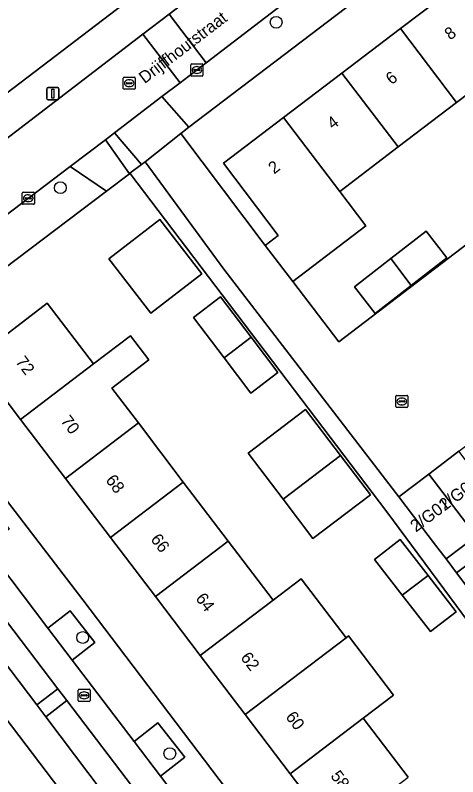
# Model space of a CAD drawing. Extents: x 160030 to 160839, y 385325 to 386450.
# Drawn here: x 160455.5 to 160492.1, y 385535.4 to 385598.3 of the extents above; entities that cross this region are included whole.
import ezdxf

# ---------------------------------------------------------------- set-up
doc = ezdxf.new("R2010")
doc.units = 0
for name, color, linetype in [('IMGEO_Berm_groen', 7, 'Continuous'), ('IMGEO_Boom', 7, 'Continuous'), ('IMGEO_Erf', 7, 'Continuous'), ('IMGEO_Fietspad_gesloten', 7, 'Continuous'), ('IMGEO_Groenvoorziening', 7, 'Continuous'), ('IMGEO_Kolk', 7, 'Continuous'), ('IMGEO_Lichtmast', 7, 'Continuous'), ('IMGEO_Openbare_ruimte_label', 7, 'Continuous'), ('IMGEO_Pand', 7, 'Continuous'), ('IMGEO_Pand_nummerreeks', 7, 'Continuous'), ('IMGEO_Parkeervlak_open', 7, 'Continuous'), ('IMGEO_Rijbaan_lokaal_gesloten', 7, 'Continuous'), ('IMGEO_Rijbaan_lokaal_open', 7, 'Continuous'), ('IMGEO_Rioolput', 7, 'Continuous'), ('IMGEO_Voetpad_open', 7, 'Continuous')]:
    doc.layers.add(name, color=color, linetype=linetype)

msp = doc.modelspace()

# ---------------------------------------------------------------- linework, layer by layer
at = {"layer": 'IMGEO_Berm_groen'}
msp.add_lwpolyline([(160447.13, 385554.756), (160457.308, 385541.366), (160459.033, 385542.706), (160443.342, 385563.345)], dxfattribs=at)
msp.add_lwpolyline([(160459.78, 385541.723), (160458.059, 385540.397), (160463.888, 385532.649), (160465.638, 385534.018)], close=True, dxfattribs=at)
at = {"layer": 'IMGEO_Boom'}
for centre in [(160477.081, 385597.751), (160459.249, 385584.086), (160461.094, 385546.937), (160468.294, 385537.344)]:
    msp.add_circle(centre, 0.489, dxfattribs=at)
at = {"layer": 'IMGEO_Erf'}
for points in [[(160541.325, 385643.407), (160500, 385611.993), (160469.864, 385589.083), (160469.192, 385588.563), (160476.184, 385579.322), (160477.257, 385580.137), (160472.72, 385586.106), (160477.69, 385589.884), (160482.522, 385593.557), (160487.355, 385597.231), (160492.187, 385600.904), (160497.019, 385604.577), (160500, 385606.843), (160501.851, 385608.25), (160503.572, 385609.559), (160502.858, 385610.499)], [(160440.459, 385581.006), (160500, 385626.337)], [(160496.829, 385594.796), (160491.998, 385591.123), (160487.165, 385587.449), (160482.333, 385583.776), (160484.501, 385580.924), (160478.458, 385576.33), (160482.263, 385571.356), (160495.041, 385581.104)], [(160464.999, 385585.276), (160464.955, 385585.243), (160463.068, 385583.814), (160446.182, 385571.066)], [(160499.726, 385539.086), (160486.228, 385557.31), (160464.999, 385585.276)], [(160481.957, 385530.81), (160478.243, 385535.687), (160474.529, 385540.564), (160470.814, 385545.441), (160467.1, 385550.318), (160463.386, 385555.194), (160459.672, 385560.071), (160455.957, 385564.949), (160452.138, 385569.963), (160458.158, 385574.548), (160461.977, 385569.533), (160465.036, 385571.862), (160466.558, 385569.862), (160463.5, 385567.533), (160465.693, 385564.654), (160469.407, 385559.778), (160473.122, 385554.901), (160476.836, 385550.025), (160479.148, 385551.785), (160482.861, 385546.907), (160483.062, 385547.06), (160486.776, 385542.184), (160484.264, 385540.271), (160487.978, 385535.394)], [(160445.996, 385569.716), (160461.114, 385550.049), (160484.853, 385518.765), (160498.893, 385500), (160500, 385498.52), (160507.161, 385489.347)], [(160493.605, 385555.304), (160491.129, 385553.423), (160491.983, 385552.267), (160494.561, 385554.205)]]:
    msp.add_lwpolyline(points, dxfattribs=at)
for points in [[(160463.243, 385578.212), (160467.466, 385581.469), (160470.929, 385576.979), (160466.71, 385573.725)], [(160486.547, 385578.231), (160489.472, 385580.494), (160491.182, 385578.282), (160488.24, 385576.006), (160485.254, 385573.697), (160483.543, 385575.908)], [(160472.486, 385575.066), (160475.01, 385571.746), (160477.225, 385568.83), (160474.988, 385567.13), (160472.774, 385570.044), (160470.249, 385573.367)], [(160477.659, 385558.354), (160474.764, 385562.164), (160479.512, 385565.772), (160482.404, 385561.965), (160484.865, 385558.725), (160480.117, 385555.117)], [(160487.498, 385550.438), (160485.217, 385553.371), (160487.332, 385555.017), (160489.631, 385552.062), (160491.96, 385549.068), (160489.827, 385547.444)]]:
    msp.add_lwpolyline(points, close=True, dxfattribs=at)
at = {"layer": 'IMGEO_Fietspad_gesloten'}
for points in [[(160472.998, 385528.276), (160467.524, 385535.472), (160465.348, 385538.333), (160460.22, 385545.074), (160458.213, 385547.717), (160453.099, 385554.455), (160450.953, 385557.282), (160445.661, 385564.255), (160443.639, 385566.902), (160443.094, 385567.626), (160440.675, 385570.838), (160437.024, 385575.695), (160434.488, 385579.069), (160434.209, 385579.434), (160431.957, 385582.38), (160424.67, 385591.91), (160423.01, 385594.08), (160417.542, 385601.244), (160415.698, 385603.667), (160409.13, 385612.299), (160407.497, 385614.445), (160405.943, 385616.479), (160403.696, 385619.461), (160402.039, 385616.699)], [(160439.79, 385567.957), (160441.538, 385565.717), (160443.342, 385563.345), (160459.033, 385542.706), (160459.78, 385541.723), (160465.638, 385534.018), (160466.586, 385532.772), (160475.085, 385521.593), (160475.646, 385520.856), (160480.979, 385513.841), (160481.709, 385512.882), (160498.314, 385491.117), (160500.146, 385488.707), (160503.656, 385484.09)]]:
    msp.add_lwpolyline(points, dxfattribs=at)
at = {"layer": 'IMGEO_Groenvoorziening'}
for points in [[(160460.068, 385549.13), (160458.213, 385547.717), (160460.22, 385545.074), (160462.101, 385546.514)], [(160467.303, 385539.888), (160465.348, 385538.333), (160467.524, 385535.472), (160469.523, 385537.051)]]:
    msp.add_lwpolyline(points, close=True, dxfattribs=at)
at = {"layer": 'IMGEO_Kolk'}
for p, q in [((160470.029, 385593.385), (160470.029, 385594.237)), ((160470.104, 385594.311), (160470.956, 385594.311)), ((160470.517, 385594.091), (160470.542, 385594.091)), ((160471.03, 385594.237), (160471.03, 385593.385)), ((160470.288, 385593.805), (160470.288, 385593.817)), ((160470.726, 385593.768), (160470.328, 385593.768)), ((160470.331, 385593.854), (160470.729, 385593.854)), ((160470.54, 385593.531), (160470.515, 385593.531)), ((160470.772, 385593.817), (160470.772, 385593.805)), ((160470.956, 385593.311), (160470.104, 385593.311)), ((160456.096, 385582.788), (160456.096, 385583.64)), ((160456.171, 385583.714), (160457.023, 385583.714)), ((160456.584, 385583.494), (160456.609, 385583.494)), ((160457.097, 385583.64), (160457.097, 385582.788)), ((160457.023, 385582.714), (160456.171, 385582.714)), ((160456.355, 385583.208), (160456.355, 385583.22)), ((160456.793, 385583.171), (160456.395, 385583.171)), ((160456.398, 385583.257), (160456.796, 385583.257)), ((160456.607, 385582.934), (160456.582, 385582.934)), ((160456.839, 385583.22), (160456.839, 385583.208)), ((160486.964, 385566.009), (160486.964, 385566.861)), ((160487.039, 385566.935), (160487.891, 385566.935)), ((160487.223, 385566.429), (160487.223, 385566.441)), ((160487.661, 385566.392), (160487.263, 385566.392)), ((160487.266, 385566.478), (160487.664, 385566.478)), ((160487.452, 385566.715), (160487.477, 385566.715)), ((160487.707, 385566.441), (160487.707, 385566.429)), ((160487.965, 385566.861), (160487.965, 385566.009)), ((160487.891, 385565.935), (160487.039, 385565.935)), ((160487.475, 385566.155), (160487.45, 385566.155))]:
    msp.add_line(p, q, dxfattribs=at)
for points in [[(160470.029, 385593.385), (160470.029, 385594.237)], [(160470.104, 385594.311), (160470.956, 385594.311)], [(160471.03, 385594.237), (160471.03, 385593.385)], [(160470.956, 385593.311), (160470.104, 385593.311)], [(160456.096, 385582.788), (160456.096, 385583.64)], [(160456.171, 385583.714), (160457.023, 385583.714)], [(160457.097, 385583.64), (160457.097, 385582.788)], [(160457.023, 385582.714), (160456.171, 385582.714)], [(160486.964, 385566.009), (160486.964, 385566.861)], [(160487.039, 385566.935), (160487.891, 385566.935)], [(160487.965, 385566.861), (160487.965, 385566.009)], [(160487.891, 385565.935), (160487.039, 385565.935)]]:
    msp.add_lwpolyline(points, dxfattribs=at)
for centre, radius, start, end in [((160470.106, 385594.235), 0.0765, 91.55205, 178.44795), ((160470.106, 385594.235), 0.0765, 91.55205, 178.44795), ((160470.954, 385594.235), 0.0765, 1.55205, 88.44795), ((160470.954, 385594.235), 0.0765, 1.55205, 88.44795), ((160470.106, 385593.387), 0.0765, 181.55205, 268.44795), ((160470.106, 385593.387), 0.0765, 181.55205, 268.44795), ((160470.328, 385593.814), 0.0403, 85.87752, 175.75265), ((160470.325, 385593.804), 0.0366, 178.93798, 274.71019), ((160470.729, 385593.811), 0.043, 264.86636, 352.45326), ((160470.733, 385593.816), 0.0386, 1.73085, 96.63898), ((160470.954, 385593.387), 0.0765, 271.55205, 358.44795), ((160470.954, 385593.387), 0.0765, 271.55205, 358.44795), ((160456.173, 385583.638), 0.0765, 91.55205, 178.44795), ((160456.173, 385583.638), 0.0765, 91.55205, 178.44795), ((160457.021, 385583.638), 0.0765, 1.55205, 88.44795), ((160457.021, 385583.638), 0.0765, 1.55205, 88.44795), ((160456.173, 385582.79), 0.0765, 181.55205, 268.44795), ((160456.173, 385582.79), 0.0765, 181.55205, 268.44795), ((160456.395, 385583.217), 0.0403, 85.87752, 175.75265), ((160456.392, 385583.207), 0.0366, 178.93798, 274.71019), ((160456.796, 385583.214), 0.043, 264.86636, 352.45326), ((160456.8, 385583.219), 0.0386, 1.73085, 96.63898), ((160457.021, 385582.79), 0.0765, 271.55205, 358.44795), ((160457.021, 385582.79), 0.0765, 271.55205, 358.44795), ((160487.041, 385566.859), 0.0765, 91.55205, 178.44795), ((160487.041, 385566.859), 0.0765, 91.55205, 178.44795), ((160487.263, 385566.438), 0.0403, 85.87752, 175.75265), ((160487.26, 385566.428), 0.0366, 178.93798, 274.71019), ((160487.664, 385566.435), 0.043, 264.86636, 352.45326), ((160487.668, 385566.44), 0.0386, 1.73085, 96.63898), ((160487.889, 385566.859), 0.0765, 1.55205, 88.44795), ((160487.889, 385566.859), 0.0765, 1.55205, 88.44795), ((160487.041, 385566.011), 0.0765, 181.55205, 268.44795), ((160487.041, 385566.011), 0.0765, 181.55205, 268.44795), ((160487.889, 385566.011), 0.0765, 271.55205, 358.44795), ((160487.889, 385566.011), 0.0765, 271.55205, 358.44795)]:
    msp.add_arc(centre, radius, start, end, dxfattribs=at)
for centre, major_axis, ratio, start_param, end_param in [((160470.516, 385593.811), (-0.387, 0.002), 0.722429, 4.712389, 7.853982), ((160470.541, 385593.811), (-0.39, 0.002), 0.717154, 1.570796, 4.712389), ((160456.583, 385583.214), (-0.387, 0.002), 0.722429, 4.712389, 7.853982), ((160456.608, 385583.214), (-0.39, 0.002), 0.717154, 1.570796, 4.712389), ((160487.451, 385566.435), (-0.387, 0.002), 0.722429, 4.712389, 7.853982), ((160487.476, 385566.435), (-0.39, 0.002), 0.717154, 1.570796, 4.712389)]:
    msp.add_ellipse(centre, major_axis=major_axis, ratio=ratio, start_param=start_param, end_param=end_param, dxfattribs=at)
at = {"layer": 'IMGEO_Lichtmast'}
for p, q in [((160458.134, 385591.455), (160458.134, 385592.255)), ((160458.134, 385592.255), (160458.134, 385591.455)), ((160458.234, 385592.355), (160459.024, 385592.355)), ((160459.024, 385592.355), (160458.234, 385592.355)), ((160459.124, 385592.255), (160459.124, 385591.455)), ((160459.124, 385591.455), (160459.124, 385592.255)), ((160459.024, 385591.355), (160458.234, 385591.355)), ((160458.234, 385591.355), (160459.024, 385591.355))]:
    msp.add_line(p, q, dxfattribs=at)
msp.add_lwpolyline([(160458.554, 385592.23), (160458.704, 385592.23), (160458.704, 385591.48), (160458.554, 385591.48), (160458.554, 385592.23)], dxfattribs=at)
for centre, start, end in [((160458.234, 385592.255), 90, 180), ((160458.234, 385592.255), 90, 180), ((160459.024, 385592.255), 0, 90), ((160459.024, 385592.255), 360, 90), ((160458.234, 385591.455), 180, 270), ((160458.234, 385591.455), 180, 270), ((160459.024, 385591.455), 270, 0), ((160459.024, 385591.455), 270, 0)]:
    msp.add_arc(centre, 0.1, start, end, dxfattribs=at)
at = {"layer": 'IMGEO_Pand'}
for points in [[(160492.187, 385600.904), (160487.355, 385597.231), (160491.998, 385591.123), (160496.829, 385594.796)], [(160487.165, 385587.449), (160491.998, 385591.123), (160487.355, 385597.231), (160482.522, 385593.557)], [(160482.522, 385593.557), (160477.69, 385589.884), (160482.333, 385583.776), (160487.165, 385587.449)], [(160477.69, 385589.884), (160472.72, 385586.106), (160477.257, 385580.137), (160476.184, 385579.322), (160478.458, 385576.33), (160484.501, 385580.924), (160482.333, 385583.776)], [(160463.243, 385578.212), (160466.71, 385573.725), (160470.929, 385576.979), (160467.466, 385581.469)], [(160491.182, 385578.282), (160489.472, 385580.494), (160486.547, 385578.231), (160488.24, 385576.006)], [(160488.24, 385576.006), (160486.547, 385578.231), (160483.543, 385575.908), (160485.254, 385573.697)], [(160461.977, 385569.533), (160458.158, 385574.548), (160452.138, 385569.963), (160455.957, 385564.949)], [(160472.486, 385575.066), (160470.249, 385573.367), (160472.774, 385570.044), (160475.01, 385571.746)], [(160461.977, 385569.533), (160455.957, 385564.949), (160459.672, 385560.071), (160465.693, 385564.654), (160463.5, 385567.533), (160466.558, 385569.862), (160465.036, 385571.862)], [(160475.01, 385571.746), (160472.774, 385570.044), (160474.988, 385567.13), (160477.225, 385568.83)], [(160477.659, 385558.354), (160482.404, 385561.965), (160479.512, 385565.772), (160474.764, 385562.164)], [(160459.672, 385560.071), (160463.386, 385555.194), (160469.407, 385559.778), (160465.693, 385564.654)], [(160482.404, 385561.965), (160477.659, 385558.354), (160480.117, 385555.117), (160484.865, 385558.725)], [(160496.082, 385557.185), (160492.186, 385562.314), (160489.709, 385560.433), (160493.605, 385555.304)], [(160491.129, 385553.423), (160493.605, 385555.304), (160489.709, 385560.433), (160487.233, 385558.552), (160490.257, 385554.571)], [(160473.122, 385554.901), (160469.407, 385559.778), (160463.386, 385555.194), (160467.1, 385550.318)], [(160487.498, 385550.438), (160489.631, 385552.062), (160487.332, 385555.017), (160485.217, 385553.371)], [(160467.1, 385550.318), (160470.814, 385545.441), (160476.836, 385550.025), (160473.122, 385554.901)], [(160491.983, 385552.267), (160494.318, 385549.161), (160496.896, 385551.099), (160494.561, 385554.205)], [(160489.631, 385552.062), (160487.498, 385550.438), (160489.827, 385547.444), (160491.96, 385549.068)], [(160479.148, 385551.785), (160476.836, 385550.025), (160470.814, 385545.441), (160474.529, 385540.564), (160482.861, 385546.907)], [(160486.776, 385542.184), (160483.062, 385547.06), (160482.861, 385546.907), (160474.529, 385540.564), (160478.243, 385535.687), (160484.264, 385540.271)], [(160487.978, 385535.394), (160484.264, 385540.271), (160478.243, 385535.687), (160481.957, 385530.81)]]:
    msp.add_lwpolyline(points, close=True, dxfattribs=at)
at = {"layer": 'IMGEO_Parkeervlak_open'}
for points in [[(160442.763, 385555.984), (160493.777, 385488.866)], [(160464.791, 385531.498), (160463.888, 385532.649), (160458.059, 385540.397), (160457.308, 385541.366), (160447.13, 385554.756)]]:
    msp.add_lwpolyline(points, dxfattribs=at)
at = {"layer": 'IMGEO_Rijbaan_lokaal_gesloten'}
msp.add_lwpolyline([(160497.695, 385483.664), (160496.401, 385485.402), (160494.164, 385488.4), (160493.777, 385488.866), (160442.763, 385555.984), (160439.656, 385560.054)], dxfattribs=at)
at = {"layer": 'IMGEO_Rijbaan_lokaal_open'}
for points in [[(160471.301, 385594.403), (160477.533, 385599.159), (160483.774, 385603.922), (160500, 385616.279), (160505.852, 385620.735), (160511.805, 385625.275), (160508.738, 385629.311), (160500, 385622.665), (160495.185, 385619.002), (160471.728, 385601.112), (160468.226, 385598.433)], [(160469.139, 385592.753), (160471.301, 385594.403), (160468.226, 385598.433), (160466.066, 385596.78)], [(160504.567, 385571.72), (160496.589, 385582.29), (160495.041, 385581.104), (160482.263, 385571.356), (160478.458, 385576.33), (160476.184, 385579.322), (160469.192, 385588.563), (160466.255, 385586.22), (160472.748, 385577.368), (160487.233, 385558.552), (160489.709, 385560.433), (160492.186, 385562.314), (160494.662, 385564.196), (160497.138, 385566.077), (160499.614, 385567.958), (160500, 385568.251), (160502.091, 385569.839)]]:
    msp.add_lwpolyline(points, close=True, dxfattribs=at)
msp.add_lwpolyline([(160443.934, 385573.865), (160454.658, 385581.746), (160460.068, 385585.848), (160462.974, 385588.052), (160463.725, 385588.621), (160467.641, 385591.609), (160469.139, 385592.753), (160466.066, 385596.78), (160451.491, 385585.629), (160440.781, 385577.777)], dxfattribs=at)
at = {"layer": 'IMGEO_Rioolput'}
for p, q in [((160464.439, 385592.292), (160464.439, 385593.144)), ((160464.514, 385593.218), (160465.366, 385593.218)), ((160464.741, 385592.761), (160465.139, 385592.761)), ((160464.927, 385592.998), (160464.952, 385592.998)), ((160465.44, 385593.144), (160465.44, 385592.292)), ((160465.366, 385592.218), (160464.514, 385592.218)), ((160464.698, 385592.712), (160464.698, 385592.724)), ((160465.136, 385592.675), (160464.738, 385592.675)), ((160464.95, 385592.438), (160464.925, 385592.438)), ((160465.182, 385592.724), (160465.182, 385592.712)), ((160460.71, 385541.735), (160460.71, 385542.587)), ((160460.785, 385542.661), (160461.637, 385542.661)), ((160461.198, 385542.441), (160461.223, 385542.441)), ((160461.711, 385542.587), (160461.711, 385541.735)), ((160460.969, 385542.155), (160460.969, 385542.167)), ((160461.407, 385542.118), (160461.009, 385542.118)), ((160461.012, 385542.204), (160461.41, 385542.204)), ((160461.221, 385541.881), (160461.196, 385541.881)), ((160461.453, 385542.167), (160461.453, 385542.155)), ((160461.637, 385541.661), (160460.785, 385541.661))]:
    msp.add_line(p, q, dxfattribs=at)
for points in [[(160464.439, 385592.292), (160464.439, 385593.144)], [(160464.514, 385593.218), (160465.366, 385593.218)], [(160465.44, 385593.144), (160465.44, 385592.292)], [(160465.366, 385592.218), (160464.514, 385592.218)], [(160460.71, 385541.735), (160460.71, 385542.587)], [(160460.785, 385542.661), (160461.637, 385542.661)], [(160461.711, 385542.587), (160461.711, 385541.735)], [(160461.637, 385541.661), (160460.785, 385541.661)]]:
    msp.add_lwpolyline(points, dxfattribs=at)
for centre, radius, start, end in [((160464.516, 385593.142), 0.0765, 91.55205, 178.44795), ((160464.516, 385593.142), 0.0765, 91.55205, 178.44795), ((160464.738, 385592.721), 0.0403, 85.87752, 175.75265), ((160465.143, 385592.723), 0.0386, 1.73085, 96.63898), ((160465.364, 385593.142), 0.0765, 1.55205, 88.44795), ((160465.364, 385593.142), 0.0765, 1.55205, 88.44795), ((160464.516, 385592.294), 0.0765, 181.55205, 268.44795), ((160464.516, 385592.294), 0.0765, 181.55205, 268.44795), ((160464.735, 385592.711), 0.0366, 178.93798, 274.71019), ((160465.139, 385592.718), 0.043, 264.86636, 352.45326), ((160465.364, 385592.294), 0.0765, 271.55205, 358.44795), ((160465.364, 385592.294), 0.0765, 271.55205, 358.44795), ((160460.787, 385542.585), 0.0765, 91.55205, 178.44795), ((160460.787, 385542.585), 0.0765, 91.55205, 178.44795), ((160461.635, 385542.585), 0.0765, 1.55205, 88.44795), ((160461.635, 385542.585), 0.0765, 1.55205, 88.44795), ((160461.009, 385542.164), 0.0403, 85.87752, 175.75265), ((160461.006, 385542.154), 0.0366, 178.93798, 274.71019), ((160461.41, 385542.161), 0.043, 264.86636, 352.45326), ((160461.414, 385542.166), 0.0386, 1.73085, 96.63898), ((160460.787, 385541.737), 0.0765, 181.55205, 268.44795), ((160460.787, 385541.737), 0.0765, 181.55205, 268.44795), ((160461.635, 385541.737), 0.0765, 271.55205, 358.44795), ((160461.635, 385541.737), 0.0765, 271.55205, 358.44795)]:
    msp.add_arc(centre, radius, start, end, dxfattribs=at)
for centre, major_axis, ratio, start_param, end_param in [((160464.926, 385592.718), (-0.387, 0.002), 0.722429, 4.712389, 7.853982), ((160464.951, 385592.718), (-0.39, 0.002), 0.717154, 1.570796, 4.712389), ((160461.197, 385542.161), (-0.387, 0.002), 0.722429, 4.712389, 7.853982), ((160461.222, 385542.161), (-0.39, 0.002), 0.717154, 1.570796, 4.712389)]:
    msp.add_ellipse(centre, major_axis=major_axis, ratio=ratio, start_param=start_param, end_param=end_param, dxfattribs=at)
at = {"layer": 'IMGEO_Voetpad_open'}
for points in [[(160477.533, 385599.159), (160471.301, 385594.403), (160469.139, 385592.753), (160467.641, 385591.609), (160469.864, 385589.083), (160500, 385611.993), (160541.325, 385643.407)], [(160466.066, 385596.78), (160468.226, 385598.433), (160471.728, 385601.112), (160495.185, 385619.002), (160500, 385622.665), (160508.738, 385629.311), (160510.954, 385630.996), (160509.815, 385633.793), (160500, 385626.337), (160440.459, 385581.006)], [(160438.718, 385580.55), (160440.781, 385577.777), (160451.491, 385585.629), (160466.066, 385596.78)], [(160446.182, 385571.066), (160463.068, 385583.814), (160460.068, 385585.848), (160454.658, 385581.746), (160443.934, 385573.865)], [(160494.318, 385549.161), (160491.983, 385552.267), (160491.129, 385553.423), (160490.257, 385554.571), (160487.233, 385558.552), (160472.748, 385577.368), (160466.255, 385586.22), (160465.952, 385585.992), (160464.999, 385585.276), (160486.228, 385557.31), (160499.726, 385539.086)], [(160507.161, 385489.347), (160500, 385498.52), (160498.893, 385500), (160484.853, 385518.765), (160461.114, 385550.049), (160445.996, 385569.716)], [(160443.094, 385567.626), (160443.639, 385566.902), (160445.502, 385568.414), (160447.528, 385565.704), (160445.661, 385564.255), (160450.953, 385557.282), (160452.825, 385558.783), (160455.01, 385555.879), (160453.099, 385554.455), (160458.213, 385547.717), (160460.068, 385549.13), (160462.101, 385546.514), (160460.22, 385545.074), (160465.348, 385538.333), (160467.303, 385539.888), (160469.523, 385537.051), (160467.524, 385535.472), (160472.998, 385528.276)]]:
    msp.add_lwpolyline(points, dxfattribs=at)
for points in [[(160469.192, 385588.563), (160469.864, 385589.083), (160467.641, 385591.609), (160463.725, 385588.621), (160465.952, 385585.992), (160466.255, 385586.22)], [(160463.725, 385588.621), (160462.974, 385588.052), (160464.955, 385585.243), (160464.999, 385585.276), (160465.952, 385585.992)], [(160460.068, 385585.848), (160463.068, 385583.814), (160464.955, 385585.243), (160462.974, 385588.052)], [(160457.308, 385541.366), (160458.059, 385540.397), (160459.78, 385541.723), (160459.033, 385542.706)]]:
    msp.add_lwpolyline(points, close=True, dxfattribs=at)

# ---------------------------------------------------------------- texts
at = {"layer": 'IMGEO_Openbare_ruimte_label'}
msp.add_text('Drijffhoutstraat', height=1, rotation=37.36253, dxfattribs=at).set_placement((160466.214, 385592.64))
at = {"layer": 'IMGEO_Pand_nummerreeks'}
for s, rotation, p in [('8', 37.2399, (160491.466, 385596.236)), ('6', 37.2399, (160486.612, 385592.546)), ('4', 37.2399, (160481.762, 385588.859)), ('2', 37.24226, (160476.909, 385585.17)), ('72', 307.25729, (160455.5, 385569.705)), ('70', 307.25923, (160459.223, 385564.812)), ('68', 307.25729, (160462.94, 385559.923)), ('2/G02', 36.44203, (160491.008, 385557.355)), ('2/G01', 36.44203, (160488.633, 385555.601)), ('66', 307.25729, (160466.657, 385555.037)), ('64', 307.25729, (160470.375, 385550.148)), ('62', 307.25729, (160474.091, 385545.263)), ('60', 307.25729, (160477.813, 385540.37)), ('58', 307.25729, (160481.531, 385535.481))]:
    msp.add_text(s, height=1, rotation=rotation, dxfattribs=at).set_placement(p)

doc.saveas('drawing.dxf')
